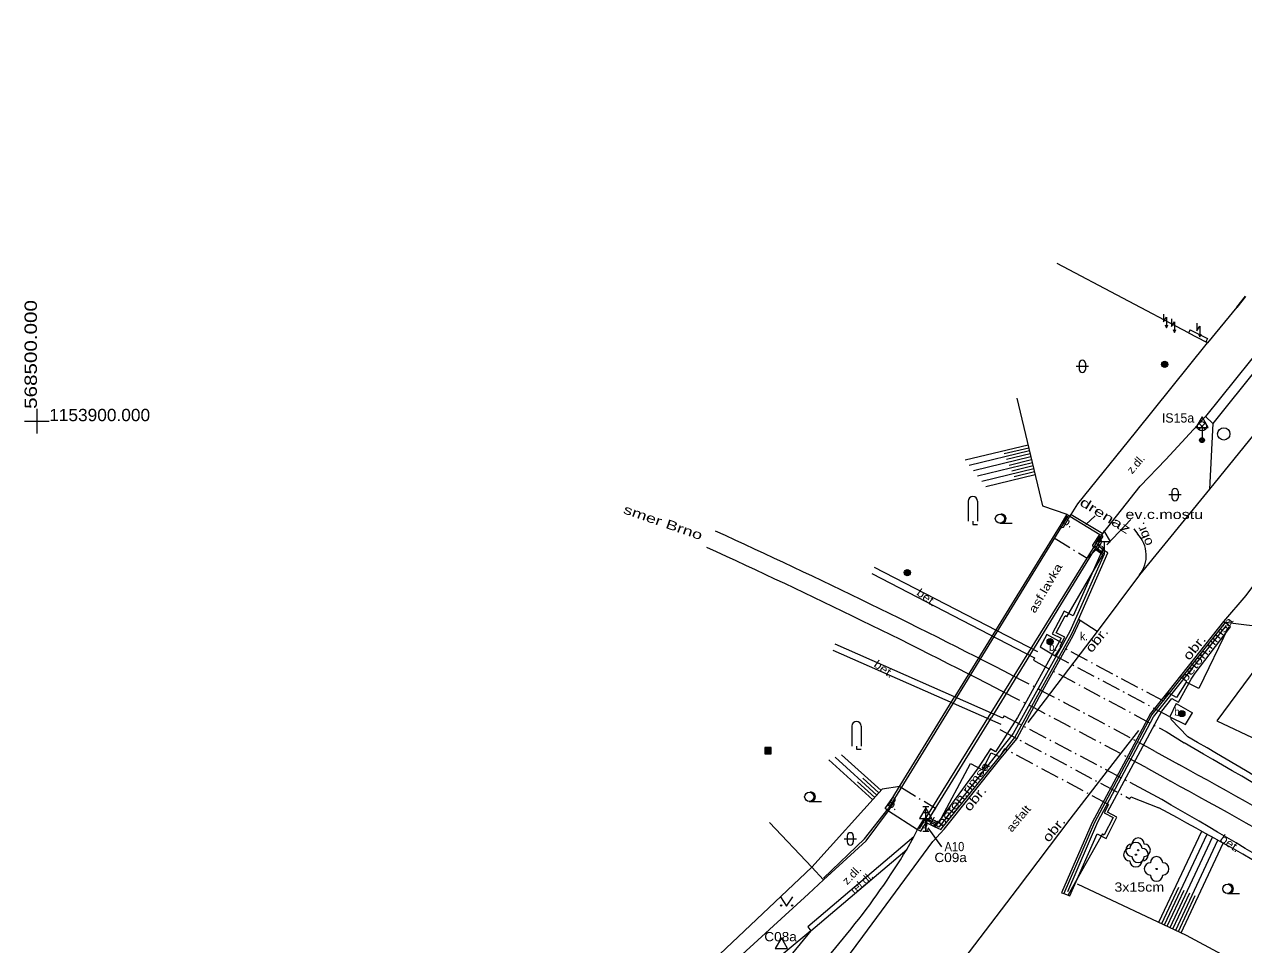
# Model space of a CAD drawing. Extents: x -568501 to -568291, y -1154101 to -1153799.
# Drawn here: x -568501 to -568402, y -1153942.5 to -1153867.8 of the extents above; entities that cross this region are included whole.
import ezdxf
from ezdxf.enums import TextEntityAlignment as Align

# ---------------------------------------------------------------- set-up
doc = ezdxf.new("R2010")
doc.units = 0
doc.header["$LTSCALE"] = 0.3
doc.linetypes.add('DOT_DASHED', pattern=[7.7, 5, -1.2, 0.3, -1.2])
for name, color, linetype, lineweight in [('10', 7, 'Continuous', 13), ('11', 7, 'Continuous', 13), ('12', 7, 'Continuous', 13), ('14', 7, 'Continuous', 13), ('15', 7, 'Continuous', 13), ('22', 7, 'Continuous', 13), ('23', 7, 'Continuous', 13), ('24', 7, 'Continuous', 13), ('25', 7, 'Continuous', 13), ('27', 7, 'Continuous', 13), ('33', 7, 'Continuous', 13), ('34', 7, 'Continuous', 13), ('36', 7, 'Continuous', 13), ('42', 7, 'Continuous', 13), ('61', 7, 'Continuous', 13), ('7', 7, 'Continuous', 13), ('8', 7, 'Continuous', 35), ('9', 7, 'Continuous', 13)]:
    doc.layers.add(name, color=color, linetype=linetype, lineweight=lineweight)
doc.layers.add('40', color=7, linetype='Continuous')

msp = doc.modelspace()

# ---------------------------------------------------------------- linework, layer by layer
at = {"layer": '10'}
for p, q in [((-568410.89, -1153908.73), (-568410.6, -1153909.16)), ((-568403.6, -1153916.28), (-568403.47, -1153916.36))]:
    msp.add_line(p, q, dxfattribs=at)
for points in [[(-568341.41, -1153838.94), (-568349.83, -1153849.41), (-568360.25, -1153862.43), (-568369.78, -1153874.42), (-568378.19, -1153884.73), (-568386.01, -1153894.27), (-568392.67, -1153902.27), (-568398.22, -1153909.37), (-568401.79, -1153914.15), (-568403.6, -1153916.28)], [(-568384.23, -1153880.16), (-568392.01, -1153889.4), (-568398.35, -1153897.64), (-568404.75, -1153905.51), (-568410.43, -1153912.49)], [(-568410.43, -1153912.49), (-568413.88, -1153917.08), (-568418.09, -1153922.63), (-568419.49, -1153924.47)], [(-568427.22, -1153934.12), (-568426.3, -1153933.12), (-568421.79, -1153927.5), (-568420.4, -1153925.8), (-568418.54, -1153922.37), (-568415.81, -1153917.41), (-568415.26, -1153916.18), (-568415.38, -1153916.1)], [(-568403.6, -1153916.28), (-568408.01, -1153921.83), (-568409.54, -1153923.75), (-568411.54, -1153927.5), (-568414.28, -1153932.58), (-568416.77, -1153938.29), (-568416.57, -1153938.36)], [(-568416.07, -1153932.32), (-568412.12, -1153927.19), (-568410.48, -1153925.11)], [(-568451.7, -1153980.29), (-568449.61, -1153977.28), (-568446.84, -1153973.45), (-568445.91, -1153972.15), (-568442.46, -1153967.27), (-568439.57, -1153963.38), (-568433.28, -1153955), (-568432.53, -1153954), (-568431.81, -1153953.03), (-568426.84, -1153946.5), (-568420.35, -1153937.98), (-568416.07, -1153932.32)], [(-568439.32, -1153950.51), (-568432.9, -1153941.84), (-568427.22, -1153934.12)]]:
    msp.add_lwpolyline(points, dxfattribs=at)
msp.add_arc((-568412.3883, -1153910.9206), 2.5095, 321.29136, 44.55359, dxfattribs=at)
at = {"layer": '11'}
for p, q in [((-568404.48, -1153900.2), (-568405.07, -1153899.62)), ((-568413.418, -1153909.12), (-568410.38, -1153905.27)), ((-568415.98, -1153907.59), (-568415.44, -1153906.71)), ((-568416.33, -1153907.55), (-568416.08, -1153907.72)), ((-568416.08, -1153907.72), (-568415.98, -1153907.59)), ((-568416.08, -1153907.72), (-568413.64, -1153909.2)), ((-568415.98, -1153907.59), (-568413.418, -1153909.12)), ((-568413.84, -1153910.05), (-568413.33, -1153910.469)), ((-568413.529, -1153909.265), (-568413.418, -1153909.12)), ((-568416.328, -1153915.891), (-568413.42, -1153910.86)), ((-568413.98, -1153910.44), (-568414.67, -1153911.13)), ((-568413.535, -1153910.711), (-568414, -1153910.31)), ((-568413.42, -1153910.86), (-568413.98, -1153910.44)), ((-568418.69, -1153918.73), (-568431.95, -1153911.89)), ((-568416.328, -1153915.891), (-568416.46, -1153915.82)), ((-568413.88, -1153917.08), (-568415.26, -1153916.18)), ((-568435.34, -1153918.6), (-568421.7, -1153924.6)), ((-568430.31, -1153930.28), (-568425.43, -1153922.37)), ((-568407.46, -1153922.93), (-568406.12, -1153923.69)), ((-568408.27, -1153925.21), (-568406.8, -1153926.13)), ((-568408.61, -1153930.73), (-568411.19, -1153929.33)), ((-568430.83, -1153931.63), (-568428.45, -1153933.15)), ((-568427.01, -1153931.43), (-568427.51, -1153932.22)), ((-568427.75, -1153932.6), (-568427.057, -1153932.936)), ((-568427.58, -1153932.35), (-568426.87, -1153932.69)), ((-568427.51, -1153932.22), (-568426.74, -1153932.62)), ((-568413.442, -1153933.51), (-568416.24, -1153938.52)), ((-568413.442, -1153933.51), (-568413.31, -1153933.58)), ((-568447.22, -1153957.51), (-568433.85, -1153941.21)), ((-568437.12, -1153941.38), (-568442.59, -1153945.91)), ((-568437.12, -1153941.38), (-568442.48, -1153947.86))]:
    msp.add_line(p, q, dxfattribs=at)
at = {"layer": '11', "linetype": 'DOT_DASHED'}
for p, q in [((-568417.37, -1153909.47), (-568414.67, -1153911.13)), ((-568408.51, -1153922.72), (-568416.87, -1153918.26)), ((-568419.05, -1153919.42), (-568408.27, -1153925.21)), ((-568407.97, -1153924), (-568417.27, -1153919.05)), ((-568421.41, -1153923.93), (-568411.19, -1153929.33)), ((-568421.78, -1153925.03), (-568411.22, -1153930.66)), ((-568412.95, -1153931.12), (-568421.38, -1153926.61)), ((-568429.91, -1153929.66), (-568427.01, -1153931.43))]:
    msp.add_line(p, q, dxfattribs=at)
at = {"layer": '11'}
for points in [[(-568381.7, -1153869.78), (-568383.21, -1153872.58), (-568387.5, -1153877.91), (-568389.32, -1153880.18), (-568394.71, -1153886.81), (-568401.41, -1153895.07), (-568405.07, -1153899.62), (-568408.29, -1153903.1), (-568410.38, -1153905.27)], [(-568384.23, -1153880.16), (-568388.74, -1153880.73), (-568394.35, -1153887.63), (-568400.75, -1153895.57), (-568404.48, -1153900.2), (-568404.75, -1153905.51)], [(-568415.44, -1153906.71), (-568410.75, -1153900.93), (-568404.91, -1153893.64)], [(-568416.33, -1153907.55), (-568416.89, -1153908.52), (-568416.73, -1153908.64), (-568416.6, -1153908.62), (-568416.08, -1153907.72)], [(-568416.89, -1153908.52), (-568417.08, -1153908.82), (-568425.43, -1153922.37)], [(-568413.4, -1153909.34), (-568413.84, -1153910.05), (-568414, -1153910.31), (-568414.2, -1153910.2), (-568414.22, -1153910.08), (-568413.64, -1153909.2)], [(-568413.64, -1153909.2), (-568413.529, -1153909.265), (-568413.4, -1153909.34)], [(-568414, -1153910.31), (-568414.19, -1153910.59), (-568422.46, -1153924.05)], [(-568432.18, -1153912.36), (-568418.95, -1153919.23), (-568419.05, -1153919.42)], [(-568416.87, -1153918.26), (-568416.49, -1153917.55), (-568417.19, -1153917.19), (-568416.46, -1153915.82)], [(-568403.19, -1153916.74), (-568405.61, -1153921.71), (-568406.63, -1153921.18), (-568407.42, -1153922.44), (-568408.09, -1153922.05), (-568408.51, -1153922.72)], [(-568416.74, -1153918.01), (-568417.96, -1153917.31), (-568418.5, -1153918.32), (-568417.27, -1153919.05), (-568416.8, -1153918.32)], [(-568421.41, -1153923.93), (-568421.53, -1153924.12), (-568435.14, -1153918.1)], [(-568407.46, -1153922.93), (-568407.97, -1153924), (-568406.7, -1153924.64), (-568406.12, -1153923.69)], [(-568427.75, -1153932.6), (-568427.58, -1153932.35), (-568427.39, -1153932.06), (-568422.46, -1153924.05)], [(-568406.5, -1153925.63), (-568407.87, -1153924.19), (-568407.8, -1153924.09)], [(-568426.74, -1153932.62), (-568424.17, -1153927.79), (-568423.19, -1153928.31), (-568422.47, -1153926.92), (-568421.78, -1153927.25), (-568421.38, -1153926.61)], [(-568432.62, -1153934.09), (-568430.83, -1153931.63), (-568431.09, -1153931.46), (-568430.48, -1153930.56), (-568430.31, -1153930.28)], [(-568430.83, -1153931.63), (-568430.28, -1153930.8), (-568430.29, -1153930.67), (-568430.48, -1153930.56)], [(-568411.22, -1153930.66), (-568411.13, -1153930.5), (-568408.87, -1153931.39)], [(-568412.95, -1153931.12), (-568413.3, -1153931.81), (-568412.57, -1153932.19), (-568413.31, -1153933.58)], [(-568428.77, -1153933.74), (-568428.45, -1153933.15), (-568428.19, -1153933.29), (-568427.75, -1153932.6)], [(-568428.45, -1153933.15), (-568427.9, -1153932.24), (-568427.75, -1153932.21), (-568427.58, -1153932.35)], [(-568451.52, -1153952.97), (-568451.46, -1153952.92), (-568445.04, -1153945.75), (-568443.66, -1153944.18), (-568437.31, -1153938.38), (-568436.1, -1153937.25), (-568432.62, -1153934.09)]]:
    msp.add_lwpolyline(points, dxfattribs=at)
for points in [[(-568427.06, -1153932.94), (-568426.57, -1153933.16), (-568421.91, -1153927.38), (-568420.56, -1153925.69), (-568418.7, -1153922.26), (-568415.95, -1153917.33), (-568415.38, -1153916.1), (-568413.01, -1153910.69), (-568413.35, -1153910.47), (-568413.53, -1153910.7), (-568415.82, -1153915.8), (-568416.54, -1153915.43), (-568417.52, -1153917.26), (-568416.8, -1153917.63), (-568420.348, -1153924.07), (-568422.13, -1153926.84), (-568422.52, -1153926.61), (-568423.54, -1153928.16)], [(-568416.57, -1153938.36), (-568416.08, -1153938.54), (-568413.88, -1153933.52), (-568413.14, -1153933.88), (-568412.28, -1153932.15), (-568413.02, -1153931.76), (-568408.62, -1153923.56), (-568407.79, -1153922.53), (-568407.25, -1153922.82), (-568406.24, -1153920.96), (-568405.9, -1153920.45), (-568403.04, -1153916.71), (-568403.47, -1153916.36), (-568407.9, -1153921.95), (-568409.42, -1153923.82), (-568411.46, -1153927.67), (-568414.09, -1153932.6)], [(-568429.34, -1153934.77), (-568428.77, -1153933.74), (-568437.36, -1153941.05), (-568437.12, -1153941.38)]]:
    msp.add_lwpolyline(points, close=True, dxfattribs=at)
for centre, radius, start, end in [((-569009.5906, -1154964.079), 1200.8724, 58.47781, 59.85365), ((-568847.5367, -1154693.8111), 885.2023, 58.27428, 60.13925), ((-568987.7107, -1154929.3603), 1154.3916, 58.50566, 59.89077), ((-568598.8116, -1154282.7187), 399.3866, 57.62556, 61.60266), ((-568477.7722, -1153905.6516), 56.5116, 321.00718, 328.98489)]:
    msp.add_arc(centre, radius, start, end, dxfattribs=at)
at = {"layer": '12'}
for p, q in [((-568409.16, -1153926.82), (-568407.23, -1153927.89)), ((-568409.89, -1153928.12), (-568407.92, -1153929.23))]:
    msp.add_line(p, q, dxfattribs=at)
for centre, radius, start, end in [((-568671.7552, -1154406.1673), 546.5586, 62.55996, 65.47223), ((-568662.8048, -1154386.9623), 523.8665, 62.45434, 65.50109), ((-568635.0051, -1154346.2032), 476.306, 58.03243, 61.43134), ((-568645.0661, -1154364.1594), 495.3805, 58.1384, 61.39848)]:
    msp.add_arc(centre, radius, start, end, dxfattribs=at)
at = {"layer": '12', "linetype": 'DOT_DASHED'}
for centre, radius, start, end in [((-568674.5323, -1154411.701), 552.7495, 61.30839, 62.56881), ((-568667.9439, -1154402.5275), 540.0503, 61.45602, 62.73461)]:
    msp.add_arc(centre, radius, start, end, dxfattribs=at)
at = {"layer": '14'}
for p, q in [((-568420.39, -1153898.14), (-568418.3, -1153906.88)), ((-568418.3, -1153906.88), (-568416.33, -1153907.55)), ((-568398.65, -1153916.93), (-568403.47, -1153916.36))]:
    msp.add_line(p, q, dxfattribs=at)
for points in [[(-568429.91, -1153929.66), (-568431.33, -1153929.89), (-568437.06, -1153936.21)], [(-568415.48, -1153937.58), (-568406.64, -1153941.73), (-568392.63, -1153949.25), (-568382.59, -1153955.78), (-568371.09, -1153963.05), (-568356.19, -1153973.32)]]:
    msp.add_lwpolyline(points, dxfattribs=at)
at = {"layer": '15'}
for p, q in [((-568419.482, -1153901.936), (-568424.601, -1153903.16)), ((-568419.366, -1153902.422), (-568424.262, -1153903.593)), ((-568419.25, -1153902.909), (-568423.923, -1153904.026)), ((-568419.424, -1153902.179), (-568421.427, -1153902.658)), ((-568419.308, -1153902.665), (-568421.222, -1153903.123)), ((-568419.133, -1153903.395), (-568423.584, -1153904.459)), ((-568419.017, -1153903.881), (-568423.245, -1153904.892)), ((-568419.192, -1153903.152), (-568421.016, -1153903.588)), ((-568419.075, -1153903.638), (-568420.811, -1153904.053)), ((-568418.959, -1153904.124), (-568420.606, -1153904.518)), ((-568418.901, -1153904.367), (-568422.906, -1153905.325)), ((-568432.098, -1153930.738), (-568435.674, -1153927.496)), ((-568431.763, -1153930.367), (-568435.156, -1153927.29)), ((-568431.427, -1153929.997), (-568434.638, -1153927.085)), ((-568431.93, -1153930.552), (-568433.324, -1153929.289)), ((-568431.595, -1153930.182), (-568432.916, -1153928.984)), ((-568408.847, -1153940.694), (-568405.376, -1153933.302)), ((-568408.394, -1153940.907), (-568404.938, -1153933.544)), ((-568407.941, -1153941.119), (-568404.5, -1153933.788)), ((-568407.489, -1153941.332), (-568404.062, -1153934.032)), ((-568407.036, -1153941.544), (-568403.625, -1153934.277)), ((-568408.62, -1153940.8), (-568407.235, -1153937.849)), ((-568408.168, -1153941.013), (-568406.788, -1153938.074)), ((-568407.715, -1153941.225), (-568406.341, -1153938.299)), ((-568407.262, -1153941.438), (-568405.895, -1153938.524))]:
    msp.add_line(p, q, dxfattribs=at)
at = {"layer": '22'}
for centre in [(-568410.54, -1153934.84), (-568410.72, -1153935.2), (-568409.04, -1153936.36)]:
    msp.add_circle(centre, 0.05, dxfattribs=at)
for centre, start, end in [((-568410.54, -1153934.34), 0, 180), ((-568411.22, -1153935.2), 90, 270), ((-568411.04, -1153934.84), 90, 270), ((-568410.72, -1153934.7), 0, 180), ((-568410.22, -1153935.2), 270, 90), ((-568410.04, -1153934.84), 270, 90), ((-568410.72, -1153935.7), 180, 0), ((-568410.54, -1153935.34), 180, 0), ((-568409.04, -1153935.86), 0, 180), ((-568409.54, -1153936.36), 90, 270), ((-568408.54, -1153936.36), 270, 90), ((-568409.04, -1153936.86), 180, 0)]:
    msp.add_arc(centre, 0.5, start, end, dxfattribs=at)
at = {"layer": '23'}
msp.add_lwpolyline([(-568398.65, -1153916.93), (-568404.16, -1153924.33), (-568394.15, -1153929.05)], dxfattribs=at)
at = {"layer": '24'}
for p, q in [((-568406.302, -1153892.574), (-568406.44, -1153892.84)), ((-568406.44, -1153892.84), (-568405.05, -1153893.56)), ((-568406.302, -1153892.574), (-568404.912, -1153893.294)), ((-568404.912, -1153893.294), (-568405.05, -1153893.56))]:
    msp.add_line(p, q, dxfattribs=at)
for points in [[(-568408.48, -1153891.304), (-568408.48, -1153891.93), (-568408.23, -1153891.555), (-568408.23, -1153892.43)], [(-568408.34, -1153892.185), (-568408.23, -1153892.43), (-568408.12, -1153892.185)], [(-568407.84, -1153891.684), (-568407.84, -1153892.31), (-568407.59, -1153891.935), (-568407.59, -1153892.81)], [(-568405.777, -1153892.039), (-568405.777, -1153892.665), (-568405.527, -1153892.29), (-568405.527, -1153893.165)], [(-568407.7, -1153892.565), (-568407.59, -1153892.81), (-568407.48, -1153892.565)], [(-568405.637, -1153892.92), (-568405.527, -1153893.165), (-568405.417, -1153892.92)]]:
    msp.add_lwpolyline(points, dxfattribs=at)
at = {"layer": '25'}
for points in [[(-568440.86, -1153927.01), (-568440.36, -1153927.01), (-568440.36, -1153926.51), (-568440.86, -1153926.51)], [(-568440.81, -1153926.96), (-568440.41, -1153926.96), (-568440.41, -1153926.56), (-568440.81, -1153926.56)], [(-568440.76, -1153926.91), (-568440.46, -1153926.91), (-568440.46, -1153926.61), (-568440.76, -1153926.61)], [(-568440.71, -1153926.86), (-568440.51, -1153926.86), (-568440.51, -1153926.66), (-568440.71, -1153926.66)], [(-568440.66, -1153926.81), (-568440.56, -1153926.81), (-568440.56, -1153926.71), (-568440.66, -1153926.71)]]:
    msp.add_lwpolyline(points, close=True, dxfattribs=at)
for centre, radius in [((-568408.38, -1153895.39), 0.25), ((-568408.38, -1153895.39), 0.2), ((-568408.38, -1153895.39), 0.15), ((-568408.38, -1153895.39), 0.1), ((-568408.38, -1153895.39), 0.05), ((-568429.29, -1153912.3), 0.25), ((-568429.29, -1153912.3), 0.2), ((-568429.29, -1153912.3), 0.15), ((-568429.29, -1153912.3), 0.1), ((-568429.29, -1153912.3), 0.05), ((-568417.69, -1153917.9), 0.25), ((-568417.69, -1153917.9), 0.2), ((-568417.69, -1153917.9), 0.15), ((-568417.69, -1153917.9), 0.1), ((-568417.69, -1153917.9), 0.05), ((-568406.99, -1153923.74), 0.25), ((-568406.99, -1153923.74), 0.2), ((-568406.99, -1153923.74), 0.15), ((-568406.99, -1153923.74), 0.1), ((-568406.99, -1153923.74), 0.05)]:
    msp.add_circle(centre, radius, dxfattribs=at)
at = {"layer": '27'}
msp.add_circle((-568403.58, -1153901.04), 0.5, dxfattribs=at)
at = {"layer": '33'}
for p, q in [((-568405.615, -1153900.68), (-568405.085, -1153900.15)), ((-568405.615, -1153900.15), (-568405.085, -1153900.68)), ((-568405.35, -1153900.79), (-568405.35, -1153901.54)), ((-568428.04, -1153931.28), (-568427.54, -1153931.28)), ((-568428.04, -1153931.78), (-568427.54, -1153931.78)), ((-568427.79, -1153933.28), (-568427.79, -1153931.28)), ((-568428.04, -1153932.28), (-568427.54, -1153932.28)), ((-568428.04, -1153933.28), (-568427.54, -1153933.28))]:
    msp.add_line(p, q, dxfattribs=at)
for centre, radius in [((-568405.35, -1153900.415), 0.375), ((-568405.35, -1153901.54), 0.2), ((-568405.35, -1153901.54), 0.1445), ((-568405.35, -1153901.54), 0.0876)]:
    msp.add_circle(centre, radius, dxfattribs=at)
at = {"layer": '34'}
for p, q in [((-568405.35, -1153900.522), (-568405.35, -1153901.54)), ((-568413.29, -1153909.782), (-568413.29, -1153910.8)), ((-568427.79, -1153932.262), (-568427.79, -1153933.28))]:
    msp.add_line(p, q, dxfattribs=at)
for points in [[(-568405.85, -1153900.522), (-568404.85, -1153900.522), (-568405.35, -1153899.656)], [(-568413.79, -1153909.782), (-568412.79, -1153909.782), (-568413.29, -1153908.916)], [(-568428.29, -1153932.262), (-568427.29, -1153932.262), (-568427.79, -1153931.396)], [(-568440.02, -1153942.832), (-568439.02, -1153942.832), (-568439.52, -1153941.966)]]:
    msp.add_lwpolyline(points, close=True, dxfattribs=at)
at = {"layer": '36'}
for p, q in [((-568415.57, -1153895.544), (-568414.57, -1153895.544)), ((-568415.32, -1153895.294), (-568415.32, -1153895.794)), ((-568414.82, -1153895.294), (-568414.82, -1153895.794)), ((-568408.045, -1153905.962), (-568407.045, -1153905.962)), ((-568407.795, -1153905.712), (-568407.795, -1153906.212)), ((-568407.295, -1153905.712), (-568407.295, -1153906.212)), ((-568424.339, -1153906.504), (-568424.339, -1153908.129)), ((-568423.589, -1153906.504), (-568423.589, -1153908.129)), ((-568421.767, -1153908.291), (-568420.767, -1153908.291)), ((-568433.796, -1153924.763), (-568433.796, -1153926.388)), ((-568433.046, -1153924.763), (-568433.046, -1153926.388)), ((-568437.253, -1153930.877), (-568436.253, -1153930.877)), ((-568434.179, -1153933.665), (-568434.179, -1153934.165)), ((-568433.679, -1153933.665), (-568433.679, -1153934.165)), ((-568434.429, -1153933.915), (-568433.429, -1153933.915)), ((-568403.292, -1153938.347), (-568402.292, -1153938.347))]:
    msp.add_line(p, q, dxfattribs=at)
for points in [[(-568423.964, -1153908.129), (-568423.964, -1153908.379), (-568423.589, -1153908.379)], [(-568433.421, -1153926.388), (-568433.421, -1153926.638), (-568433.046, -1153926.638)], [(-568439.593, -1153938.621), (-568439.093, -1153939.371), (-568438.593, -1153938.621)]]:
    msp.add_lwpolyline(points, dxfattribs=at)
for centre, radius in [((-568421.7665, -1153907.9154), 0.375), ((-568437.2548, -1153930.5015), 0.375), ((-568403.292, -1153937.9721), 0.375), ((-568439.5431, -1153939.3206), 0.05), ((-568438.6437, -1153939.3206), 0.05)]:
    msp.add_circle(centre, radius, dxfattribs=at)
for centre, radius, start, end in [((-568415.0713, -1153895.2958), 0.25, 0, 180), ((-568415.0713, -1153895.7958), 0.25, 180, 0), ((-568407.5464, -1153905.7134), 0.25, 0, 180), ((-568423.9641, -1153906.5028), 0.375, 0, 180), ((-568407.5464, -1153906.2134), 0.25, 180, 0), ((-568421.6415, -1153907.9154), 0.375, 260.40593, 99.59407), ((-568433.4212, -1153924.762), 0.375, 0, 180), ((-568437.1298, -1153930.5015), 0.375, 260.40593, 99.59407), ((-568433.9285, -1153933.6663), 0.25, 0, 180), ((-568433.9285, -1153934.1663), 0.25, 180, 0), ((-568403.167, -1153937.9721), 0.375, 260.40593, 99.59407)]:
    msp.add_arc(centre, radius, start, end, dxfattribs=at)
at = {"layer": '42'}
for p, q in [((-568414.798, -1153908.382), (-568414.018, -1153907.674)), ((-568413.089, -1153910.05), (-568411.133, -1153907.979)), ((-568427.621, -1153933.033), (-568426.514, -1153934.558))]:
    msp.add_line(p, q, dxfattribs=at)
at = {"layer": '61'}
for p, q in [((-568500, -1153899), (-568500, -1153901)), ((-568501, -1153900), (-568499, -1153900))]:
    msp.add_line(p, q, dxfattribs=at)
at = {"layer": '7'}
for p, q in [((-568406.44, -1153892.84), (-568417.13, -1153887.2)), ((-568440.494, -1153932.576), (-568437.06, -1153936.21)), ((-568436.1, -1153937.25), (-568437.06, -1153936.21))]:
    msp.add_line(p, q, dxfattribs=at)
for points in [[(-568402.52, -1153890.74), (-568404.91, -1153893.64), (-568405.05, -1153893.56)], [(-568437.06, -1153936.21), (-568444.53, -1153943.27), (-568446.16, -1153945), (-568450.39, -1153949.74)]]:
    msp.add_lwpolyline(points, dxfattribs=at)
at = {"layer": '8'}
msp.add_line((-568402.52, -1153890.74), (-568401.83, -1153889.84), dxfattribs=at)
at = {"layer": '9'}
for p, q in [((-568416.25, -1153907.72), (-568430.85, -1153931.48)), ((-568413.29, -1153910.8), (-568414.062, -1153910.116)), ((-568432.77, -1153933.91), (-568430.85, -1153931.48)), ((-568428.3, -1153933.11), (-568427.829, -1153932.308)), ((-568426.72, -1153932.96), (-568427.829, -1153932.308)), ((-568436.09, -1153937.11), (-568432.77, -1153933.91))]:
    msp.add_line(p, q, dxfattribs=at)
for points in [[(-568427.829, -1153932.308), (-568414.062, -1153910.116), (-568413.58, -1153909.34)], [(-568413.29, -1153910.8), (-568416.08, -1153917.08), (-568420.68, -1153925.36), (-568426.72, -1153932.96)], [(-568416.26, -1153938.18), (-568413.82, -1153932.54), (-568409.29, -1153924.02), (-568403.36, -1153916.6)]]:
    msp.add_lwpolyline(points, dxfattribs=at)

# ---------------------------------------------------------------- texts
at = {"layer": '40'}
for s, rotation, width, p in [('z.dl.', 49.573, 1.05, (-568411.025, -1153904.333)), ('b.', 329.358, 1.2, (-568416.754, -1153908.247)), ('b.', 329.358, 1.2, (-568414.105, -1153909.88)), ('b.', 329.358, 1.2, (-568413.976, -1153910.411)), ('asf.lavka', 59.616, 1.3, (-568418.921, -1153915.645)), ('bet.', 323.922, 1.2, (-568428.604, -1153914.072)), ('beton.rimsa', 52.209, 1.4, (-568406.667, -1153921.254)), ('bet.', 323.922, 1.2, (-568432.069, -1153919.872)), ('beton.rimsa', 52.209, 1.4, (-568426.442, -1153932.999)), ('b.', 329.358, 1.2, (-568430.959, -1153931.207)), ('asfalt', 50.073, 1.2, (-568420.803, -1153933.426)), ('b.', 329.358, 1.2, (-568428.293, -1153932.863)), ('b.', 329.358, 1.2, (-568427.538, -1153932.674)), ('bet.', 323.922, 1.2, (-568403.966, -1153934.035)), ('z.dl.', 46.41, 1.1, (-568434.175, -1153937.703))]:
    msp.add_text(s, height=0.65, rotation=rotation, dxfattribs=dict(at, width=width)).set_placement(p)
for s, width, p in [('b.', 0.9, (-568417.766, -1153918.653)), ('k.', 0.95, (-568415.251, -1153917.788)), ('b.', 0.9, (-568407.61, -1153923.921))]:
    msp.add_text(s, height=0.65, dxfattribs=dict(at, width=width)).set_placement(p)
msp.add_text('rel.dl.', height=0.65, rotation=42.165, dxfattribs=at).set_placement((-568433.572, -1153938.443))
at = {"layer": '42'}
msp.add_text('IS15a', height=0.75, dxfattribs=at).set_placement((-568407.298, -1153900.113), align=Align.CENTER)
for s, rotation, width, p in [('smer Brno', 340.832, 1.45, (-568449.2551, -1153908.563)), ('drenaz', 328.215, 1.5, (-568413.4, -1153907.9877)), ('obr.', 113.277, 1.15, (-568409.7145, -1153909.0332)), ('obr.', 50.935, 1.3, (-568413.613, -1153917.9863)), ('obr.', 50.935, 1.3, (-568405.679, -1153918.6123)), ('obr.', 50.935, 1.3, (-568423.515, -1153930.8753)), ('obr.', 50.935, 1.3, (-568417.096, -1153933.3773))]:
    msp.add_text(s, height=0.75, rotation=rotation, dxfattribs=dict(at, width=width)).set_placement(p, align=Align.CENTER)
for s, width, p in [('ev.c.mostu', 1.3, (-568408.418, -1153907.943)), ('A10', 0.9, (-568425.465, -1153934.917)), ('C09a', 1.1, (-568425.7695, -1153935.803)), ('3x15cm', 1.15, (-568410.448, -1153938.204)), ('C08a', 1.1, (-568439.588, -1153942.232))]:
    msp.add_text(s, height=0.75, dxfattribs=dict(at, width=width)).set_placement(p, align=Align.CENTER)
at = {"layer": '61', "width": 1.25}
msp.add_text('568500.000', height=1, rotation=90, dxfattribs=at).set_placement((-568500, -1153899))
at = {"layer": '61', "width": 1.05}
msp.add_text('1153900.000', height=1, dxfattribs=at).set_placement((-568499, -1153900))

doc.saveas('drawing.dxf')
